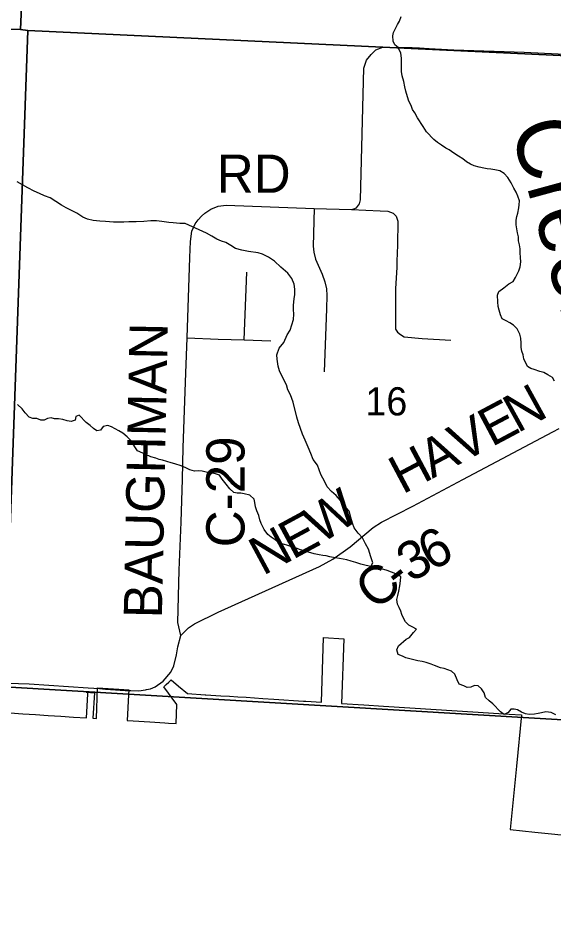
# Model space of a CAD drawing. Extents: x -7.5 to 26.5, y 3.5 to 25.5.
# Drawn here: x -3.216 to -2.42, y 21.822 to 23.173 of the extents above; entities that cross this region are included whole.
import ezdxf

# ---------------------------------------------------------------- set-up
doc = ezdxf.new("R2010")
doc.units = 0
for name, color, linetype in [('GM_X_Corporation', 7, 'Continuous'), ('GM_X_County_Road', 7, 'Continuous'), ('GM_X_County_Road_Text', 7, 'Continuous'), ('GM_X_Minor_River', 7, 'Continuous'), ('GM_X_Minor_River_Text', 7, 'Continuous'), ('GM_X_Section_Text', 7, 'Continuous'), ('GM_X_Township_Road', 7, 'Continuous')]:
    doc.layers.add(name, color=color, linetype=linetype)

msp = doc.modelspace()

# ---------------------------------------------------------------- linework, layer by layer
at = {"layer": 'GM_X_Corporation'}
for points in [[(-4.138, 24.1781), (-3.1693, 24.148), (-3.2132, 23.1565), (-4.1729, 23.1886)], [(-3.1693, 24.148), (-2.147, 24.1207), (-2.1999, 23.1078), (-3.2023, 23.155), (-3.2132, 23.1565)], [(-4.1729, 23.1886), (-3.2132, 23.1565), (-3.2023, 23.155), (-3.2367, 22.18), (-4.2212, 22.2025)], [(-3.2023, 23.155), (-2.1999, 23.1078), (-2.2479, 22.1217), (-3.2367, 22.18)], [(-3.2367, 22.18), (-2.2479, 22.1217), (-2.268, 21.1618), (-3.2602, 21.1789)]]:
    msp.add_lwpolyline(points, close=True, dxfattribs=at)
msp.add_lwpolyline([(-3.2286, 22.1412), (-3.2097, 22.14), (-3.1908, 22.1388), (-3.1719, 22.1376), (-3.153, 22.1364), (-3.1341, 22.1351), (-3.1151, 22.1339), (-3.1128, 22.1689), (-3.1128, 22.1694), (-3.1129, 22.1699), (-3.1131, 22.1703), (-3.1134, 22.1708), (-3.1137, 22.1711), (-3.1141, 22.1714), (-3.1145, 22.1717), (-3.115, 22.1718), (-3.1155, 22.1719), (-3.1032, 22.1711), (-3.1056, 22.1333), (-3.1003, 22.133), (-3.0984, 22.1784), (-3.067, 22.1764), (-3.0518, 22.1754), (-3.0523, 22.1679), (-3.0547, 22.1301), (-3.0454, 22.1295), (-3.0208, 22.1279), (-2.9985, 22.1265), (-2.9933, 22.1262), (-2.9816, 22.1254), (-2.9806, 22.1538), (-3.0002, 22.18), (-2.9963, 22.1832), (-2.9926, 22.1867), (-2.9893, 22.1904), (-2.978, 22.181), (-2.9646, 22.1699), (-2.9385, 22.1682), (-2.9377, 22.1682), (-2.9153, 22.1668), (-2.9023, 22.1659), (-2.89, 22.1651), (-2.8777, 22.1644), (-2.8654, 22.1636), (-2.8531, 22.1628), (-2.8363, 22.1617), (-2.7926, 22.1589), (-2.789, 22.1587), (-2.7658, 22.1573), (-2.7626, 22.2532), (-2.7324, 22.2515), (-2.7358, 22.1553), (-2.7026, 22.1532), (-2.6735, 22.1513), (-2.5951, 22.1463), (-2.5406, 22.1429), (-2.4868, 22.1394), (-2.4682, 22.1382), (-2.4759, 22.0622), (-2.4855, 21.9678), (-2.4486, 21.964), (-2.3846, 21.9575)], dxfattribs=at)
at = {"layer": 'GM_X_County_Road'}
for points in [[(-2.9745, 22.256), (-2.9791, 22.2753), (-2.9771, 22.3531), (-2.9744, 22.4244), (-2.9724, 22.4887), (-2.9712, 22.5354), (-2.9672, 22.646), (-2.9652, 22.6984), (-2.9616, 22.8179), (-2.9604, 22.8418), (-2.9582, 22.857), (-2.9533, 22.8678), (-2.9489, 22.874), (-2.9442, 22.879), (-2.9391, 22.8836), (-2.9301, 22.8897), (-2.9195, 22.8939), (-2.9074, 22.8955), (-2.7766, 22.8904), (-2.721, 22.8889), (-2.7174, 22.8902), (-2.7137, 22.8915), (-2.7091, 22.8977), (-2.7079, 22.9037), (-2.7027, 23.0989), (-2.6986, 23.111), (-2.692, 23.1194), (-2.6885, 23.123)], [(-2.6885, 23.123), (-2.685, 23.1266), (-2.6744, 23.1301), (-2.631, 23.1298), (-2.6198, 23.1291)], [(-2.6198, 23.1291), (-2.6056, 23.1283), (-2.5689, 23.1263), (-2.4645, 23.1228), (-2.2014, 23.11)], [(-3.0256, 22.1759), (-3.0199, 22.1771), (-3.0127, 22.1801), (-3.001, 22.1882), (-2.9898, 22.2016), (-2.985, 22.2114), (-2.981, 22.2273), (-2.9791, 22.2396), (-2.9745, 22.256), (-2.9633, 22.2677), (-2.9545, 22.2736), (-2.9193, 22.2909), (-2.7686, 22.3585), (-2.749, 22.3694), (-2.7232, 22.3879), (-2.6887, 22.4165), (-2.6767, 22.4245), (-2.6299, 22.4484), (-2.5554, 22.4881), (-2.4221, 22.5586), (-2.4125, 22.5636)], [(-3.4843, 22.1889), (-3.2712, 22.1863), (-3.2487, 22.1857), (-3.2, 22.1843), (-3.1124, 22.1784), (-3.0958, 22.1773), (-3.0867, 22.1766)], [(-3.0867, 22.1766), (-3.0573, 22.1746), (-3.0493, 22.1744), (-3.0371, 22.1741), (-3.0274, 22.1755), (-3.0256, 22.1759)]]:
    msp.add_lwpolyline(points, dxfattribs=at)
at = {"layer": 'GM_X_Minor_River'}
for points in [[(-2.4723, 22.8914), (-2.4718, 22.8963), (-2.4716, 22.902), (-2.4737, 22.9089), (-2.4766, 22.9151), (-2.4798, 22.9209), (-2.4838, 22.9286), (-2.4889, 22.9367), (-2.4944, 22.9426), (-2.5007, 22.9466), (-2.5079, 22.9483), (-2.514, 22.9489), (-2.5197, 22.9498), (-2.5246, 22.9507), (-2.5314, 22.9521), (-2.5386, 22.9538), (-2.5442, 22.9566), (-2.5502, 22.9602), (-2.5558, 22.9642), (-2.5621, 22.9682), (-2.5689, 22.9726), (-2.5759, 22.9777), (-2.5808, 22.9802), (-2.5875, 22.9849), (-2.5935, 22.9885), (-2.5987, 22.9932), (-2.6094, 23.0046), (-2.6145, 23.0123), (-2.6228, 23.0255), (-2.6272, 23.0328), (-2.6305, 23.0379), (-2.6326, 23.0436), (-2.6358, 23.0502), (-2.6379, 23.0567), (-2.6403, 23.0647), (-2.6416, 23.0716), (-2.6433, 23.0793), (-2.6457, 23.0877), (-2.6466, 23.0942), (-2.6468, 23.1002), (-2.6467, 23.1063), (-2.6468, 23.1139), (-2.6477, 23.1215), (-2.6517, 23.1296), (-2.6569, 23.134), (-2.6594, 23.139), (-2.6599, 23.147), (-2.6586, 23.1522), (-2.6558, 23.1582), (-2.6525, 23.1638), (-2.6497, 23.1687), (-2.6472, 23.1758)], [(-2.6924, 22.3585), (-2.6896, 22.3641), (-2.6924, 22.3729), (-2.6958, 22.3844), (-2.7004, 22.3926), (-2.7047, 22.4015), (-2.7113, 22.4082), (-2.7171, 22.4163), (-2.7196, 22.4229), (-2.7223, 22.4313), (-2.7247, 22.4409), (-2.7327, 22.4499), (-2.7374, 22.4566), (-2.744, 22.464), (-2.751, 22.4703), (-2.7573, 22.477), (-2.7608, 22.4843), (-2.7669, 22.4956), (-2.7717, 22.5094), (-2.7779, 22.5176), (-2.7814, 22.5265), (-2.7857, 22.5361), (-2.7899, 22.5462), (-2.7938, 22.5554), (-2.8, 22.5724), (-2.8024, 22.5804), (-2.8078, 22.6027), (-2.8116, 22.6138), (-2.8155, 22.6212), (-2.8179, 22.6285), (-2.8233, 22.6389), (-2.8282, 22.6494), (-2.8299, 22.6566), (-2.8318, 22.6666), (-2.832, 22.6731), (-2.8286, 22.6832), (-2.8219, 22.6914), (-2.8166, 22.703), (-2.8122, 22.7101), (-2.81, 22.7176), (-2.8075, 22.7259), (-2.8069, 22.7335), (-2.8074, 22.7404), (-2.8072, 22.7468), (-2.8061, 22.7563), (-2.8055, 22.7627), (-2.8053, 22.7707), (-2.8065, 22.778), (-2.81, 22.7865), (-2.8159, 22.7943), (-2.8262, 22.8034), (-2.8354, 22.8124), (-2.8447, 22.8184), (-2.8533, 22.8229), (-2.8596, 22.8246), (-2.874, 22.8266), (-2.8842, 22.8285), (-2.8936, 22.8314), (-2.9003, 22.8358), (-2.9081, 22.8399), (-2.9145, 22.842), (-2.9212, 22.8449), (-2.9287, 22.8493), (-2.9365, 22.8538), (-2.9683, 22.8685), (-2.9763, 22.8684), (-2.9861, 22.8691), (-2.9925, 22.8697), (-3.0031, 22.8712), (-3.0107, 22.8722), (-3.0194, 22.8721), (-3.0297, 22.8713), (-3.0411, 22.8709), (-3.0521, 22.8709), (-3.0593, 22.8704), (-3.0673, 22.8702), (-3.0749, 22.8701), (-3.0866, 22.8712), (-3.095, 22.8719), (-3.1052, 22.8726), (-3.1135, 22.8748), (-3.1206, 22.8777), (-3.1295, 22.8837), (-3.1452, 22.8918), (-3.1519, 22.8958), (-3.169, 22.9063), (-3.1772, 22.9096), (-3.1847, 22.9129), (-3.1926, 22.9166), (-3.2019, 22.9211), (-3.2101, 22.9259), (-3.2179, 22.93)], [(-2.4192, 22.6343), (-2.4224, 22.6394), (-2.4292, 22.6437), (-2.4352, 22.647), (-2.4412, 22.6487), (-2.4495, 22.6516), (-2.4544, 22.6529), (-2.4593, 22.6557), (-2.465, 22.6672), (-2.466, 22.673), (-2.4677, 22.6787), (-2.4687, 22.6841), (-2.4689, 22.6905), (-2.4694, 22.6981), (-2.4711, 22.7039), (-2.4751, 22.712), (-2.4802, 22.7171), (-2.4858, 22.7206), (-2.4911, 22.7238), (-2.4971, 22.7267), (-2.4996, 22.7325), (-2.5016, 22.7397), (-2.503, 22.7451), (-2.5036, 22.7519), (-2.504, 22.7618), (-2.502, 22.7671), (-2.4949, 22.7729), (-2.4871, 22.7788), (-2.4809, 22.7824), (-2.4773, 22.7879), (-2.4725, 22.798), (-2.4704, 22.804), (-2.4694, 22.8116), (-2.47, 22.8177), (-2.4705, 22.8249), (-2.4703, 22.8306), (-2.4713, 22.8367), (-2.4727, 22.8425), (-2.4729, 22.8485), (-2.4742, 22.8546), (-2.4755, 22.8604), (-2.4765, 22.8665), (-2.4763, 22.8733), (-2.4754, 22.8786), (-2.4741, 22.8839), (-2.4723, 22.8914)], [(-3.1727, 22.5787), (-3.1781, 22.5763), (-3.183, 22.576), (-3.1887, 22.5785), (-3.1948, 22.5787), (-3.2, 22.5804), (-3.2063, 22.587), (-3.2107, 22.5932), (-3.2174, 22.5995)], [(-2.6361, 22.2714), (-2.6409, 22.2765), (-2.6437, 22.2822), (-2.6462, 22.2876), (-2.648, 22.2926), (-2.6501, 22.2976), (-2.6526, 22.3026), (-2.6536, 22.3095), (-2.6522, 22.3155), (-2.6509, 22.3223), (-2.6491, 22.3302), (-2.6481, 22.3374), (-2.648, 22.3439), (-2.6554, 22.3479), (-2.6682, 22.3528), (-2.6731, 22.3541), (-2.6799, 22.3559), (-2.6868, 22.3572), (-2.6924, 22.3585), (-2.6992, 22.3602), (-2.7072, 22.3624), (-2.7147, 22.3649), (-2.7215, 22.3666), (-2.7279, 22.3687), (-2.7336, 22.3697), (-2.7389, 22.3706), (-2.7453, 22.3715), (-2.7533, 22.3733), (-2.7586, 22.3746), (-2.7639, 22.3752), (-2.7692, 22.3761), (-2.7768, 22.3775), (-2.785, 22.38), (-2.7907, 22.3821), (-2.7967, 22.3834), (-2.8035, 22.3859), (-2.8088, 22.3876), (-2.8171, 22.3905), (-2.8243, 22.3926), (-2.8299, 22.3947), (-2.8347, 22.3982), (-2.8403, 22.4022), (-2.8452, 22.4061), (-2.851, 22.4139), (-2.8553, 22.4224), (-2.8574, 22.4282), (-2.8588, 22.4347), (-2.862, 22.4416), (-2.8637, 22.4473), (-2.8647, 22.4538), (-2.8657, 22.4588), (-2.8723, 22.4647), (-2.8806, 22.4668), (-2.8856, 22.4677), (-2.8909, 22.4679), (-2.8962, 22.4685), (-2.9018, 22.4739), (-2.9076, 22.481), (-2.9131, 22.4883), (-2.9171, 22.4942), (-2.9232, 22.4962), (-2.9281, 22.4972), (-2.9372, 22.499), (-2.9432, 22.5003), (-2.9485, 22.5008), (-2.9546, 22.5006), (-2.9614, 22.5024), (-2.9674, 22.5052), (-2.9742, 22.5084), (-2.9836, 22.5114), (-2.9889, 22.5127), (-3.0021, 22.5169), (-3.007, 22.5178), (-3.0119, 22.5195), (-3.0191, 22.5216), (-3.027, 22.5249), (-3.039, 22.5306), (-3.043, 22.5364), (-3.0488, 22.5453), (-3.0544, 22.5512), (-3.061, 22.5567), (-3.067, 22.5603), (-3.0723, 22.5635), (-3.0779, 22.5663), (-3.0831, 22.5684), (-3.0904, 22.5667), (-3.094, 22.5611), (-3.0994, 22.5605), (-3.1046, 22.5637), (-3.1094, 22.5681), (-3.1154, 22.5728), (-3.1257, 22.5837), (-3.1307, 22.5816), (-3.1316, 22.5763), (-3.1378, 22.5743), (-3.1435, 22.5752), (-3.1499, 22.5769), (-3.1567, 22.5779), (-3.1624, 22.5781), (-3.1677, 22.5797), (-3.1727, 22.5787)], [(-2.4174, 22.1382), (-2.4241, 22.1418), (-2.4321, 22.1428), (-2.4386, 22.1415), (-2.4436, 22.1405), (-2.4489, 22.1392), (-2.457, 22.1387), (-2.4626, 22.14), (-2.4686, 22.1424), (-2.4743, 22.1457), (-2.4795, 22.147), (-2.4845, 22.1467), (-2.4884, 22.1419), (-2.4942, 22.1391), (-2.4998, 22.143), (-2.5109, 22.1548), (-2.5165, 22.1591), (-2.522, 22.1642), (-2.5241, 22.1711), (-2.5277, 22.1769), (-2.5329, 22.1816), (-2.5383, 22.1818), (-2.5437, 22.1797), (-2.5494, 22.1791), (-2.5543, 22.1812), (-2.561, 22.184), (-2.5639, 22.1902), (-2.5674, 22.1987), (-2.5726, 22.203), (-2.5779, 22.205), (-2.5836, 22.2071), (-2.5888, 22.2084), (-2.5979, 22.2117), (-2.6028, 22.2138), (-2.6103, 22.2163), (-2.616, 22.2176), (-2.6224, 22.2186), (-2.6285, 22.2203), (-2.6345, 22.2216), (-2.6402, 22.2229), (-2.6454, 22.2254), (-2.6515, 22.2278), (-2.6535, 22.2351), (-2.6514, 22.2411), (-2.6397, 22.2506), (-2.6347, 22.2531), (-2.6288, 22.2605), (-2.6244, 22.2657), (-2.6308, 22.2689), (-2.6361, 22.2714)]]:
    msp.add_lwpolyline(points, dxfattribs=at)
at = {"layer": 'GM_X_Township_Road'}
msp.add_line((-2.8805, 22.6953), (-2.8766, 22.7961), dxfattribs=at)
for points in [[(-2.7766, 22.8904), (-2.778, 22.8347), (-2.7769, 22.8257), (-2.7744, 22.8155), (-2.7645, 22.7932), (-2.7608, 22.7818), (-2.7584, 22.7712), (-2.7577, 22.7612), (-2.7583, 22.7416), (-2.7615, 22.648)], [(-2.721, 22.8889), (-2.6784, 22.8872), (-2.6669, 22.8868), (-2.6591, 22.8839), (-2.6545, 22.8793), (-2.652, 22.8716), (-2.6525, 22.8363), (-2.6537, 22.8125), (-2.6539, 22.8032), (-2.6555, 22.7718), (-2.6555, 22.7115), (-2.6527, 22.7068), (-2.6485, 22.7033), (-2.643, 22.6998), (-2.6161, 22.6973), (-2.5735, 22.6949)], [(-2.9652, 22.6984), (-2.9192, 22.6965), (-2.8805, 22.6953), (-2.8409, 22.694)]]:
    msp.add_lwpolyline(points, dxfattribs=at)

# ---------------------------------------------------------------- texts
at = {"layer": 'GM_X_County_Road_Text'}
for s, height, rotation, p in [('RD', 0.05682, 0, (-2.9213, 22.9139)), ('BAUGHMAN', 0.05682, 88.8396, (-3.0029, 22.2814)), ('N', 0.0568, 28.8747, (-2.4744, 22.5563)), ('E', 0.0568, 28.0102, (-2.5127, 22.5358)), ('V', 0.0568, 28.0039, (-2.5569, 22.5124)), ('C-29', 0.05682, 90, (-2.8801, 22.3873)), ('A', 0.0568, 28.0071, (-2.601, 22.4889)), ('H', 0.0568, 28.0073, (-2.6452, 22.4654)), ('W', 0.0568, 33.0053, (-2.7671, 22.391)), ('E', 0.0568, 28.3858, (-2.8087, 22.3683)), ('N', 0.0568, 28.3221, (-2.8528, 22.3445)), ('6', 0.0568, 27.5952, (-2.6031, 22.3511)), ('3', 0.0568, 28.5448, (-2.6336, 22.3345)), ('C', 0.0568, 40.0497, (-2.6852, 22.2918)), ('-', 0.0568, 38.1283, (-2.6499, 22.3215))]:
    msp.add_text(s, height=height, rotation=rotation, dxfattribs=at).set_placement(p)
at = {"layer": 'GM_X_Minor_River_Text'}
msp.add_text('Creek', height=0.0947, rotation=285.2738, dxfattribs=at).set_placement((-2.4852, 23.0129))
at = {"layer": 'GM_X_Section_Text'}
msp.add_text('16', height=0.04186, rotation=0, dxfattribs=at).set_placement((-2.7005, 22.5832))

doc.saveas('drawing.dxf')
